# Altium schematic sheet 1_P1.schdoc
size 431 x 309 mm; Symbol: Sheet-Symbol_A3; Device: Sheet-Symbol_A3; @Page Name: P1; @Create Date: 2023-05-01; @Page Count: 4; @Page No: 1; @Project Name: 3.7寸墨水屏; @Schematic Name: Schematic1_1; @Update Date: 2023-06-10; Company: 嘉立创EDA; Page Size: A3; Version: V1.0
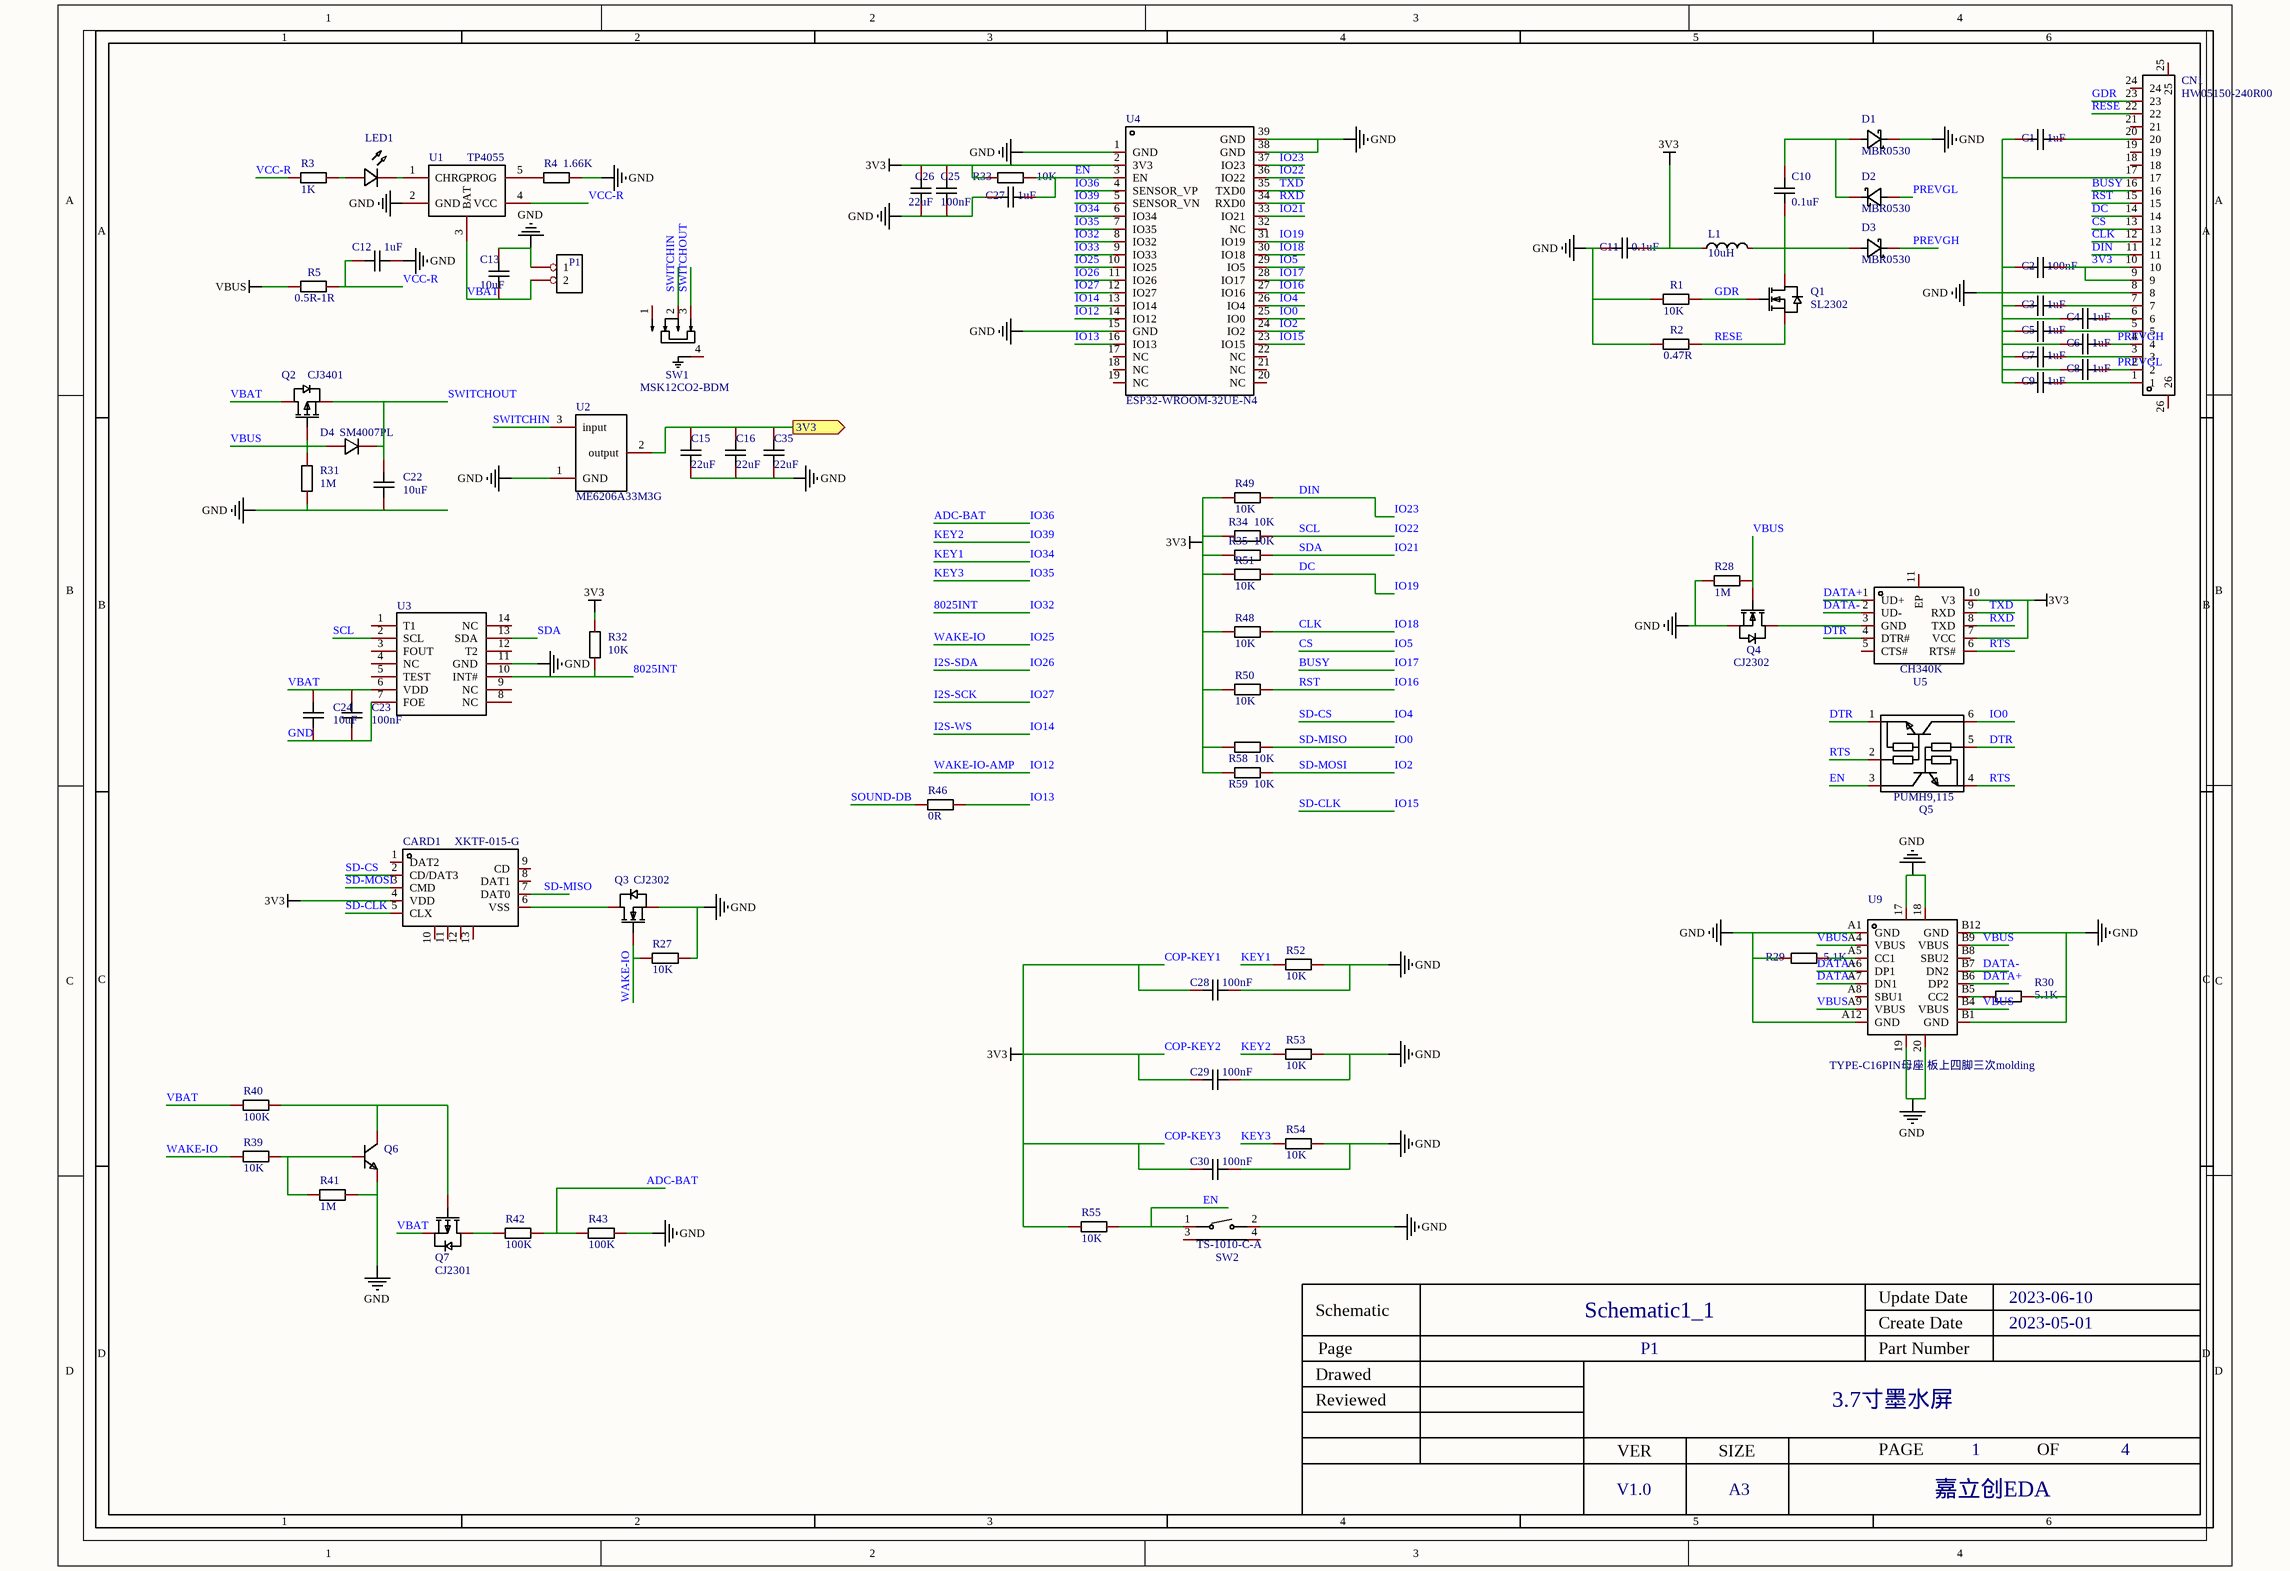
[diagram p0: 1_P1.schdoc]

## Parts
C1  1uF  [C0603]
C2  100nF  [C0603]
C3  1uF  [C0603]
C4  1uF  [C0603]
C5  1uF  [C0603]
C6  1uF  [C0603]
C7  1uF  [C0603]
C8  1uF  [C0603]
C9  1uF  [C0603]
C10  0.1uF  [C0603]
C11  0.1uF  [C0603]
C12  1uF  [C0603]
C13  10uF  [C0603]
C15  22uF  [C0603]
C16  22uF  [C0603]
C22  10uF  [C0603]
C23  100nF  [C0603]
C24  10uF  [C0603]
C25  100nF  [C0603]
C26  22uF  [C0603]
C27  1uF  [C0603]
C28  100nF  [C0603]
C29  100nF  [C0603]
C30  100nF  [C0603]
C35  22uF  [C0603]
CARD1  XKTF-015-G  [TF-SMD_XKTF-015-N]
CN1  HW05150-240R00  [FPC-SMD_24P-P0.50_HW05150-240R00]
D1  MBR0530  [SOD-123FL_L2.7-W1.8-LS3.7-RD]
D2  MBR0530  [SOD-123FL_L2.7-W1.8-LS3.7-RD]
D3  MBR0530  [SOD-123FL_L2.7-W1.8-LS3.7-RD]
D4  SM4007PL  [SOD-123F_L2.8-W1.8-LS3.7-RD]
L1  10uH  [IND-SMD_L3.5-W3.0]
LED1  LED_0603-B  [LED_0603]  (value not drawn)
P1  弯针1.25*2  [CON1.5*2-90]  (value not drawn)
Q1  SL2302  [SOT-23-3_L3.0-W1.7-P0.95-LS2.9-BR]
Q2  CJ3401  [SOT-23-3_L2.9-W1.6-P1.90-LS2.8-BR]
Q3  CJ2302  [SOT-23-3_L2.9-W1.3-P1.90-LS2.4-BR]
Q4  CJ2302  [SOT-23-3_L2.9-W1.3-P1.90-LS2.4-BR]
Q5  PUMH9,115  [SOT-363_L2.0-W1.3-P0.65-LS2.1-BL]
Q6  S8050_SOT_NPN  [S8050_SOT-23]  (value not drawn)
Q7  CJ2301  [SOT-23-3_L2.9-W1.3-P1.90-LS2.4-BR]
R1  10K  [R0603]
R2  0.47R  [R0603]
R3  1K  [R0603]
R4  1.66K  [R0603]
R5  0.5R-1R  [R0603]
R27  10K  [R0603]
R28  1M  [R0603]
R29  5.1K  [R0603]
R30  5.1K  [R0603]
R31  1M  [R0603]
R32  10K  [R0603]
R33  10K  [R0603]
R34  10K  [R0603]
R35  10K  [R0603]
R39  10K  [R0603]
R40  100K  [R0603]
R41  1M  [R0603]
R42  100K  [R0603]
R43  100K  [R0603]
R46  0R  [R0603]
R48  10K  [R0603]
R49  10K  [R0603]
R50  10K  [R0603]
R51  10K  [R0603]
R52  10K  [R0603]
R53  10K  [R0603]
R54  10K  [R0603]
R55  10K  [R0603]
R58  10K  [R0603]
R59  10K  [R0603]
SW1  MSK12CO2-BDM  [SW-SMD_MSK12CO2-BDM]
SW2  TS-1010-C-A  [KEY-SMD_TX-1010-X-X]
U1  TP4055  [SOT-23-5_L3.0-W1.7-P0.95-LS2.8-BR]
U2  ME6206A33M3G  [SOT-23-3_L2.9-W1.6-P1.90-LS2.8-BR]
U3  RX8025T-UB  [SOIC-14_L10.1-W5.0-P1.27-LS7.4-BL]  (value not drawn)
U4  ESP32-WROOM-32UE-N4  [WIFI-SMD_ESP32-WROOM-32UE-A]
U5  CH340K  [ESOP-10_L4.9-W3.9-P1.00-LS6.2-BL-EP]
U9  TYPE-C16PIN母座 板上四脚三次molding  [USB-SMD_TYPE-C16PIN]

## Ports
3V3 (out)

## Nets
3V3: C2.2 C11.2 C25.2 C26.2 C28.1 C29.1 C30.1 CARD1.4(VDD) CN1.9 CN1.10 L1.1 R32.2 R33.1 R34.1 R35.1 R48.1 R49.1 R50.1 R51.1 R55.1 R58.1 R59.1 U4.2(3V3) U5.7(VCC) U5.10(V3)  [also labelled COP-KEY1, COP-KEY2, COP-KEY3]
GND: C1.1 C2.1 C3.1 C4.1 C5.1 C6.1 C7.1 C8.1 C9.1 C11.1 C12.2 C13.2 C15.1 C16.1 C22.1 C23.1 C24.1 C25.1 C26.1 C27.1 C28.2 C29.2 C30.2 C35.1 CN1.8 CN1.17 D1.1 P1.1 Q3.2(S) Q4.2(S) Q6.2 R1.1 R2.1 R4.2 R27.2 R28.1 R29.1 R30.2 R31.1 R41.2 R43.2 R52.2 R53.2 R54.2 SW2.2 U1.2(GND) U2.1(GND) U3.7(FOE) U3.11(GND) U4.1(GND) U4.15(GND) U4.38(GND) U4.39(GND) U9.17 U9.18 U9.19 U9.20 U9.A1(GND) U9.A12(GND) U9.B1(GND) U9.B12(GND)
VBUS: D4.2(A) Q2.1(G) Q4.1(G) R5.1 R28.2 R31.2 U9.A4(VBUS) U9.A9(VBUS) U9.B4(VBUS) U9.B9(VBUS)
3V3: C15.2 C16.2 C35.2 U2.2(output) ; port 3V3  [a separate net that carries the same name]
8025INT: R32.1 U3.10(INT#) U4.8(IO32)  [also labelled IO32]
ADC-BAT: R42.2 R43.1 U4.4(SENSOR_VP)  [also labelled IO36]
BUSY: CN1.16 U4.28(IO17)  [also labelled IO17]
CLK: CN1.12 R48.2 U4.30(IO18)  [also labelled IO18]
CS: CN1.13 U4.29(IO5)  [also labelled IO5]
DATA+: U5.1(UD+) U9.A6(DP1) U9.B6(DP2)
DATA-: U5.2(UD-) U9.A7(DN1) U9.B7(DN2)
DC: CN1.14 R51.2 U4.31(IO19)  [also labelled IO19]
DIN: CN1.11 R49.2 U4.37(IO23)  [also labelled IO23]
DTR: Q5.1(E1) Q5.5(B2) U5.4(DTR#)
EN: C27.2 Q5.3(C2) R33.2 R55.2 SW2.1 U4.3(EN)
GDR: CN1.23 Q1.1(G) R1.2
I2S-SCK: U4.12(IO27)  [also labelled IO27]
I2S-SDA: U4.11(IO26)  [also labelled IO26]
I2S-WS: U4.13(IO14)  [also labelled IO14]
IO0: CARD1.7(DAT0) Q5.6(C1) R58.2 U4.25(IO0)  [also labelled SD-MISO]
IO2: CARD1.3(CMD) R59.2 U4.24(IO2)  [also labelled SD-MOSI]
IO4: CARD1.2(CD/DAT3) U4.26(IO4)  [also labelled SD-CS]
IO12: U4.14(IO12)  [also labelled WAKE-IO-AMP]
IO13: R46.2 U4.16(IO13)
IO15: CARD1.5(CLX) U4.23(IO15)  [also labelled SD-CLK]
IO16: CN1.15 R50.2 U4.27(IO16)  [also labelled RST]
IO21: R35.2 U3.13(SDA) U4.33(IO21)  [also labelled SDA]
IO22: R34.2 U3.2(SCL) U4.36(IO22)  [also labelled SCL]
IO25: Q3.1(G) R27.1 R39.1 U4.10(IO25)  [also labelled WAKE-IO]
IO33: U4.9(IO33)
IO34: R52.1 U4.6(IO34)  [also labelled KEY1]
IO35: R54.1 U4.7(IO35)  [also labelled KEY3]
IO39: R53.1 U4.5(SENSOR_VN)  [also labelled KEY2]
PREVGH: C6.2 CN1.4 D3.1
PREVGL: C8.2 CN1.2 D2.2
RESE: CN1.22 Q1.2(S) R2.2
RTS: Q5.2(B1) Q5.4(E2) U5.6(RTS#)
RXD: U4.34(RXD0) U5.8(TXD)
SOUND-DB: R46.1
SWITCHIN: SW1.2 U2.3(input)
SWITCHOUT: C22.2 D4.1(C) Q2.2(S) SW1.3
TXD: U4.35(TXD0) U5.9(RXD)
VBAT: C13.1 C23.2 C24.2 P1.2 Q2.3(D) Q7.2(S) R40.1 U1.3(BAT) U3.6(VDD)
VCC-R: C12.1 R3.1 R5.2 U1.4(VCC)
NetC1_2: C1.2 CN1.20
NetC3_2: C3.2 CN1.7
NetC4_2: C4.2 CN1.6
NetC5_2: C5.2 CN1.5
NetC7_2: C7.2 CN1.3
NetC9_2: C9.2 CN1.1
NetC10_1: C10.1 D3.2 L1.2 Q1.3(D)
NetC10_2: C10.2 D1.2 D2.1
NetCARD1_6: CARD1.6(VSS) Q3.3(D)
NetLED1_1: LED1.1(C) U1.1(CHRG)
NetLED1_2: LED1.2(A) R3.2
NetQ4_3: Q4.3(D) U5.3(GND)
NetQ6_1: Q6.1 R39.2 R41.1
NetQ6_3: Q6.3 Q7.1(G) R40.2
NetQ7_3: Q7.3(D) R42.1
NetR4_1: R4.1 U1.5(PROG)
NetR29_2: R29.2 U9.A5(CC1)
NetR30_1: R30.1 U9.B5(CC2)

Not connected (* = marked no-connect by the designer): CARD1 1(DAT2) 8(DAT1) 9(CD) 10(EP) 11(EP) 12(EP) 13(EP); CN1 18 19 21 24 25 26; SW1 1 4; SW2 3 4; U3 1(T1) 3(FOUT) 4(NC) 5(TEST) 8(NC) 9(NC) 12(T2) 14(NC); U4 17(NC) 18(NC) 19(NC) 20(NC) 21(NC) 22(NC) 32(NC); U5 5(CTS#) 11(EP); U9 A8(SBU1) B8(SBU2)

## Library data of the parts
C1-C13 C15 C16 C22-C30 C35 = CAP_0603: Symbol: CapAcitance; Convert to PCB: yes
CARD1 = XKTF-015-G: 卡连接方式:自弹式;卡类型:MicroSD卡(TF卡);连接器类型:卡座;本体最大高度:2mm;触头材质:铜合金;触头镀层:金;工作温度范围:-25℃~+90℃;焊接温度(最大值):260℃;; Manufacturer: XKB Connectivity(中国星坤); Add into BOM: yes; Card Connection Mode: 自弹式; Connector Type: 卡座; Maximum Body Height: 2mm; Welding Temperature (Max): 260℃
CN1 = HW05150-240R00: Add into BOM: yes
D1-D3 = MBR0530: 直流反向耐压(Vr):30V;平均整流电流(Io):500mA;正向压降(Vf):550mV@0.5A;反向电流(Ir):20uA@30V;; Manufacturer: LGE(鲁光); Symbol: MBR0530_C2983233; Add into BOM: yes; Reverse Voltage (Vr): 30V; Average Rectified Current (Io): 500mA
D4 = SM4007PL_C64898: 二极管配置:-;直流反向耐压(Vr):1kV;平均整流电流(Io):1A;正向压降(Vf):1.1V@1A;反向电流(Ir):10uA@1kV;; Manufacturer: MDD; Add into BOM: yes; Reverse Voltage (Vr): 1kV; Average Rectified Current (Io): 1A
L1 = SCCD32-100KT: 电感值:10uH;精度:±10%;额定电流:-;; Manufacturer: Yanchuang(研创); Add into BOM: yes; Tolerance: ±10%
LED1 = LED_0603-B: Symbol: LED_B; Convert to PCB: yes
P1 = 弯针1.25*2: Symbol: CON2; Pin Type: IN; Add into BOM: yes
Q1 = SL2302: 类型:N沟道;漏源电压(Vdss):20V;连续漏极电流(Id):2.8A;功率(Pd):400mW;导通电阻(RDS(on)@Vgs,Id):35mΩ@4.5V,3.6A;; Manufacturer: Slkor(萨科微); Add into BOM: yes; Type: N沟道; Drain Source Voltage (Vdss): 20V; Continuous Drain Current (Id): 2.8A; Power Dissipation (Pd): 400mW; Gate Threshold Voltage (Vgs(th)@Id): 950mV@50uA
Q2 = CJ3401: 类型:P沟道;漏源电压(Vdss):30V;连续漏极电流(Id):4.2A;功率(Pd):350mW;导通电阻(RDS(on)@Vgs,Id):65mΩ@10V,4.2A;; Manufacturer: CJ(江苏长电/长晶); Add into BOM: yes; Type: P沟道; Drain Source Voltage (Vdss): 30V; Power Dissipation (Pd): 350mW; Gate Threshold Voltage (Vgs(th)@Id): 1.3V@250uA
Q3 Q4 = CJ2302: 类型:N沟道;漏源电压(Vdss):20V;连续漏极电流(Id):2.1A;功率(Pd):400mW;导通电阻(RDS(on)@Vgs,Id):35mΩ@4.5V,3.6A;阈值电压(Vgs(th)@Id):950mV@250uA;栅极电荷(Qg@Vgs):4nC@4.5V;输入电容(Ciss@Vds):300pF@10V;反向传输电容(Crss@Vds):80pF@10V;工作温度:-55℃~+150℃@(Tj);; Manufacturer: CJ(江苏长电/长晶); Add into BOM: yes; Type: N沟道; Drain Source Voltage (Vdss): 20V; Continuous Drain Current (Id): 2.1A; Power Dissipation (Pd): 400mW
Q5 = PUMH9,115: 晶体管类型:2个NPN-预偏置;功率(Pd):300mW;集电极电流(Ic):100mA;集射极击穿电压(Vceo):50V;; Manufacturer: Nexperia(安世); Add into BOM: yes; Power Dissipation (Pd): 300mW; Collector Current (Ic): 100mA; Collector-Emitter Breakdown Voltage (Vceo): 50V
Q6 = S8050_SOT_NPN: Symbol: NPN; Convert to PCB: yes
Q7 = CJ2301: 类型:P沟道;漏源电压(Vdss):20V;连续漏极电流(Id):2.3A;功率(Pd):400mW;导通电阻(RDS(on)@Vgs,Id):90mΩ@4.5V,2.8A;阈值电压(Vgs(th)@Id):700mV@250uA;栅极电荷(Qg@Vgs):3.3nC@4.5V;输入电容(Ciss@Vds):405pF@10V;反向传输电容(Crss@Vds):55pF@10V;工作温度:-55℃~+150℃@(Tj);; Manufacturer: CJ(江苏长电/长晶); Add into BOM: yes; Type: P沟道; Drain Source Voltage (Vdss): 20V; Continuous Drain Current (Id): 2.3A; Power Dissipation (Pd): 400mW
R1-R5 R27-R35 R39-R43 R46 R48-R55 R58 R59 = Res_0603: Symbol: 电阻; Convert to PCB: yes
SW1 = MSK12CO2-BDM: Manufacturer: SHOU HAN(首韩); Add into BOM: yes
SW2 = TS-1010-C-A: 触点电流:50mA;额定电压(DC):12V;绝缘电阻:-;电路结构:单刀单掷;安装方式:卧贴;带灯:无;作用力:260gf;机械寿命:10万次;带支架:否;; Manufacturer: XKB Connectivity(中国星坤); Add into BOM: yes; Contact Current: 50mA; Voltage Rating (DC): 12V; Circuit: 单刀单掷; Actuator Style: 矩形按钮; Actuator/Cap Color: 黑色; With Lamp: 无; Operating Force: 260gf; Mechanical Life: 10万次; Switch Length: 2mm; Switch Width: 4mm; Switch Height: 3.5mm; Strike Gundam: 否
U1 = TP4055: 500mA 线性锂离子电池充电芯片; Manufacturer: TOPPOWER(南京拓微); Add into BOM: yes
U2 = ME6206A33M3G: 输出类型:固定;输出极性:正;最大输入电压:6V;输出电压:3.3V;输出电流:300mA;电源纹波抑制比(PSRR):50dB@(1kHz);; Manufacturer: MICRONE(南京微盟); Add into BOM: yes; Output Type: 固定; Output Polarity: 正; Number of Outputs: 1; Maximum Input Voltage: 6V; Output Voltage: 3.3V; Dropout Voltage: 380mV@(200mA); Output Current: 300mA
U3 = RX8025T-UB: 时钟芯片类型:Clock/Calendar;存储器容量:-;时间格式:HH:MM:SS;日期格式:YY-MM-DD;接口类型:I2C;; Manufacturer: EPSON(爱普生); Add into BOM: yes; Interface: I2C; Voltage - Supply: 1.8V ~ 5.5V; Current - Timekeeping (Max): 3.4uA @ 5V
U4 = ESP32-WROOM-32UE-N4_C2934568: Manufacturer: ESPRESSIF(乐鑫); Symbol: ESP32-WROOM-32UE(4MB)_C2934568; Add into BOM: yes
U5 = CH340K: 应用功能:-;接口协议:-;; Manufacturer: WCH(南京沁恒); Add into BOM: yes
U9 = TYPE-C16PIN母座 板上四脚三次molding: Add into BOM: yes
